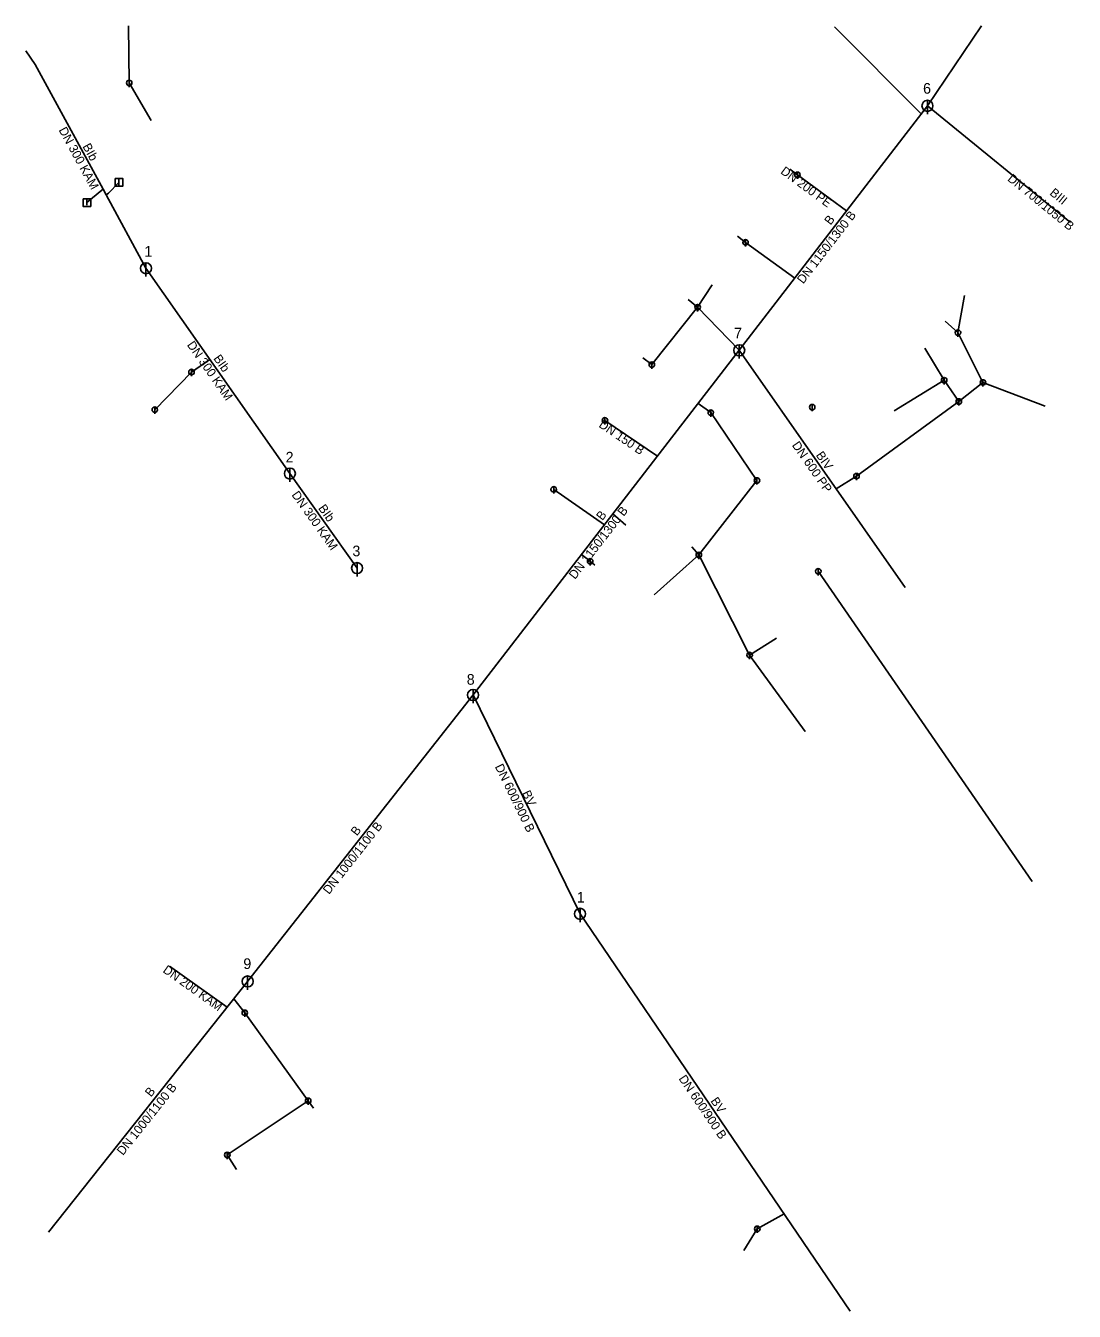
# Model space of a CAD drawing. Extents: x -464767 to -464576, y -1094411 to -1094178.
import ezdxf

# ---------------------------------------------------------------- set-up
doc = ezdxf.new("R2010")
doc.units = 0
for name, color, linetype in [('_pripojka_kanal_destova_prevzato_z_dokumentace_', 7, 'Continuous'), ('_pripojka_kanal_jednotna_prevzato_z_dokumentace_', 7, 'Continuous'), ('_pripojka_kanal_jednotna_priblizne_', 7, 'Continuous'), ('_stoka_jednotna_smvak_prevzato_z_dokumentace_', 7, 'Continuous'), ('Default', 7, 'Continuous'), ('MoLevel 119', 7, 'Continuous'), ('MoLevel 120', 7, 'Continuous'), ('MoLevel 124', 7, 'Continuous'), ('MoLevel 126', 7, 'Continuous'), ('MoLevel 57', 7, 'Continuous'), ('MoLevel 63', 7, 'Continuous'), ('MoLevel 68', 7, 'Continuous'), ('MoLevel 69', 7, 'Continuous')]:
    doc.layers.add(name, color=color, linetype=linetype)

# ---------------------------------------------------------------- blocks, each defined once
blk = doc.blocks.new('_vpust_')
at = {"layer": 'Default'}
blk.add_line((0, 0.000025), (0, -0.000025), dxfattribs=at)
blk.add_lwpolyline([(-0.000035, 0.000035), (0.000035, 0.000035), (0.000035, -0.000035), (-0.000035, -0.000035), (-0.000035, 0.000035)], dxfattribs=at)
blk = doc.blocks.new('_sachta_kanal_prip_')
at = {"layer": 'Default'}
blk.add_line((0, 0.00005), (0, -0.000075), dxfattribs=at)
blk.add_circle((0, 0), 0.00005, dxfattribs=at)
blk = doc.blocks.new('_sachta_kanal_prevzato_z_dokumentace_')
at = {"layer": 'Default'}
blk.add_line((0, 0.00005), (0, -0.000075), dxfattribs=at)
blk.add_circle((0, 0), 0.00005, dxfattribs=at)

msp = doc.modelspace()

# ---------------------------------------------------------------- linework, layer by layer
at = {"layer": '_pripojka_kanal_destova_prevzato_z_dokumentace_'}
for points in [[(-464749.66, -1094205.95), (-464751.57, -1094207.94), (-464751.98, -1094208.2)], [(-464755.46, -1094209.61), (-464752.78, -1094207.36), (-464752.49, -1094207.21)]]:
    msp.add_lwpolyline(points, dxfattribs=at)
at = {"layer": '_pripojka_kanal_jednotna_prevzato_z_dokumentace_'}
for p, q in [((-464619.92, -1094177.74), (-464604.16, -1094193.51)), ((-464628.02, -1094203.58), (-464626.62, -1094204.58)), ((-464626.62, -1094204.58), (-464617.72, -1094211.12)), ((-464637.49, -1094215.73), (-464636.03, -1094216.83)), ((-464636.03, -1094216.83), (-464627.11, -1094223.33)), ((-464642.07, -1094224.53), (-464644.72, -1094228.6)), ((-464653.03, -1094239), (-464644.72, -1094228.6)), ((-464646.44, -1094227.2), (-464644.72, -1094228.6)), ((-464644.72, -1094228.6), (-464637.18, -1094236.41)), ((-464597.52, -1094233.21), (-464592.99, -1094242.24)), ((-464736.5, -1094240.36), (-464733.17, -1094238.06)), ((-464654.63, -1094237.76), (-464653.03, -1094239)), ((-464743.16, -1094247.18), (-464736.5, -1094240.36)), ((-464592.99, -1094242.24), (-464597.36, -1094245.7)), ((-464581.71, -1094246.57), (-464592.99, -1094242.24)), ((-464597.36, -1094245.7), (-464615.92, -1094259.23)), ((-464633.97, -1094260.02), (-464642.34, -1094247.72)), ((-464661.53, -1094249.13), (-464652.01, -1094255.62)), ((-464615.92, -1094259.23), (-464619.59, -1094261.55)), ((-464670.81, -1094261.64), (-464661.61, -1094268.05)), ((-464664.21, -1094274.68), (-464665.77, -1094273.44)), ((-464663.38, -1094275.37), (-464664.21, -1094274.68)), ((-464622.85, -1094276.5), (-464584.08, -1094332.75)), ((-464726.84, -1094356.57), (-464728.83, -1094354.05)), ((-464715.34, -1094372.53), (-464726.84, -1094356.57)), ((-464730.01, -1094382.35), (-464715.34, -1094372.53)), ((-464714.38, -1094373.89), (-464715.34, -1094372.53)), ((-464728.31, -1094385.02), (-464730.01, -1094382.35))]:
    msp.add_line(p, q, dxfattribs=at)
for points in [[(-464642.34, -1094247.72), (-464642.34, -1094247.72), (-464644.62, -1094246.05)], [(-464644.51, -1094273.52), (-464644.51, -1094273.52), (-464633.97, -1094260.02)], [(-464635.3, -1094291.68), (-464635.3, -1094291.68), (-464644.51, -1094273.52)], [(-464625.24, -1094305.57), (-464625.24, -1094305.57), (-464635.3, -1094291.68)]]:
    msp.add_lwpolyline(points, dxfattribs=at)
at = {"layer": '_pripojka_kanal_jednotna_priblizne_'}
for p, q in [((-464747.79, -1094187.91), (-464747.91, -1094177.54)), ((-464743.79, -1094194.73), (-464747.79, -1094187.91)), ((-464596.32, -1094226.5), (-464597.52, -1094233.21)), ((-464599.83, -1094231.13), (-464597.52, -1094233.21)), ((-464603.55, -1094236.05), (-464600.02, -1094241.84)), ((-464609.09, -1094247.39), (-464600.02, -1094241.84)), ((-464600.02, -1094241.84), (-464597.36, -1094245.7)), ((-464657.77, -1094268.12), (-464660.1, -1094266.1)), ((-464652.62, -1094280.74), (-464644.51, -1094273.52)), ((-464645.75, -1094272.04), (-464644.51, -1094273.52)), ((-464630.4, -1094288.62), (-464635.3, -1094291.68)), ((-464740.49, -1094348.1), (-464730.01, -1094355.53)), ((-464633.91, -1094395.75), (-464629.05, -1094393.06)), ((-464636.36, -1094399.67), (-464633.91, -1094395.75))]:
    msp.add_line(p, q, dxfattribs=at)
at = {"layer": '_stoka_jednotna_smvak_prevzato_z_dokumentace_'}
for p, q in [((-464603.05, -1094192.07), (-464593.24, -1094177.54)), ((-464637.18, -1094236.41), (-464603.05, -1094192.07)), ((-464577.13, -1094213.22), (-464603.05, -1094192.07)), ((-464718.66, -1094258.76), (-464744.75, -1094221.53)), ((-464685.45, -1094298.93), (-464637.18, -1094236.41)), ((-464607.1, -1094279.41), (-464637.18, -1094236.41)), ((-464706.47, -1094275.92), (-464718.66, -1094258.76)), ((-464726.32, -1094350.89), (-464685.45, -1094298.93)), ((-464666.04, -1094338.62), (-464685.45, -1094298.93)), ((-464617.06, -1094410.71), (-464666.04, -1094338.62)), ((-464762.44, -1094396.33), (-464726.32, -1094350.89))]:
    msp.add_line(p, q, dxfattribs=at)
msp.add_lwpolyline([(-464744.75, -1094221.53), (-464751.98, -1094208.2), (-464752.49, -1094207.21), (-464764.84, -1094184.6), (-464766.56, -1094182.1)], dxfattribs=at)

# ---------------------------------------------------------------- block references
at = {"layer": 'MoLevel 119', "xscale": 20000, "yscale": 20000}
for p in [(-464603.05, -1094192.07), (-464744.75, -1094221.53), (-464637.18, -1094236.41), (-464718.66, -1094258.76), (-464706.47, -1094275.92), (-464685.45, -1094298.93), (-464666.04, -1094338.62), (-464726.32, -1094350.89)]:
    msp.add_blockref('_sachta_kanal_prevzato_z_dokumentace_', p, dxfattribs=at)
at = {"layer": 'MoLevel 57', "xscale": 10000, "yscale": 10000}
for p in [(-464747.79, -1094187.91), (-464626.62, -1094204.58), (-464636.03, -1094216.83), (-464644.72, -1094228.6), (-464597.52, -1094233.21), (-464653.03, -1094239), (-464736.5, -1094240.36), (-464600.02, -1094241.84), (-464592.99, -1094242.24), (-464597.36, -1094245.7), (-464743.16, -1094247.18), (-464642.34, -1094247.72), (-464623.94, -1094246.72), (-464661.53, -1094249.13), (-464633.97, -1094260.02), (-464615.92, -1094259.23), (-464670.81, -1094261.64), (-464644.51, -1094273.52), (-464664.21, -1094274.68), (-464622.85, -1094276.5), (-464635.3, -1094291.68), (-464726.84, -1094356.57), (-464715.34, -1094372.53), (-464730.01, -1094382.35), (-464633.91, -1094395.75)]:
    msp.add_blockref('_sachta_kanal_prip_', p, dxfattribs=at)
at = {"layer": 'MoLevel 63', "xscale": 20000, "yscale": 20000}
for p in [(-464749.66, -1094205.95), (-464755.46, -1094209.61)]:
    msp.add_blockref('_vpust_', p, dxfattribs=at)

# ---------------------------------------------------------------- texts
at = {"layer": 'MoLevel 120'}
for s, p in [('6', (-464603.84, -1094189.87)), ('1', (-464745.05, -1094219.44)), ('7', (-464638.11, -1094234.25)), ('2', (-464719.43, -1094256.76)), ('3', (-464707.32, -1094273.77)), ('8', (-464686.58, -1094297.07)), ('1', (-464666.62, -1094336.57)), ('9', (-464727.1, -1094348.63))]:
    msp.add_text(s, height=1.93, dxfattribs=at).set_placement(p)
at = {"layer": 'MoLevel 124'}
msp.add_text('DN 200 KAM', height=1.605, rotation=324.667, dxfattribs=at).set_placement((-464741.82, -1094349.12))
at = {"layer": 'MoLevel 126'}
for s, rotation, p in [('DN 200 PE', 323.6815, (-464629.81, -1094204.23)), ('DN 150 B', 325.7072, (-464662.78, -1094250.22))]:
    msp.add_text(s, height=1.605, rotation=rotation, dxfattribs=at).set_placement(p)
at = {"layer": 'MoLevel 68'}
for s, height, rotation, p in [('DN 300 KAM', 1.605, 298.6442, (-464760.63, -1094196.45)), ('DN 700/1050 B', 1.6049, 320.7959, (-464588.65, -1094205.53)), ('DN 1150/1300 B', 1.6049, 52.4133, (-464625.57, -1094224.47)), ('DN 300 KAM', 1.605, 305.022, (-464737.39, -1094235.44)), ('DN 600 PP', 1.605, 304.9741, (-464627.69, -1094253.63)), ('DN 300 KAM', 1.605, 305.389, (-464718.42, -1094262.64)), ('DN 1150/1300 B', 1.6049, 52.3292, (-464666.95, -1094278.06)), ('DN 600/900 B', 1.6049, 296.0605, (-464681.52, -1094311.91)), ('DN 1000/1100 B', 1.6049, 51.8126, (-464711.56, -1094335.2)), ('DN 1000/1100 B', 1.6049, 51.519, (-464748.93, -1094382.54)), ('DN 600/900 B', 1.6049, 304.1933, (-464648.23, -1094368.52))]:
    msp.add_text(s, height=height, rotation=rotation, dxfattribs=at).set_placement(p)
at = {"layer": 'MoLevel 69'}
for s, height, rotation, p in [('BIb', 1.605, 298.6442, (-464756.31, -1094199.41)), ('BIII', 1.605, 320.7959, (-464581.01, -1094208.09)), ('B', 1.6, 52.4133, (-464620.62, -1094213.81)), ('BIb', 1.605, 305.022, (-464732.59, -1094237.89)), ('BIV', 1.605, 304.9741, (-464623.35, -1094255.43)), ('BIb', 1.605, 305.389, (-464713.59, -1094265.06)), ('B', 1.6, 52.3292, (-464661.99, -1094267.4)), ('BV', 1.605, 296.0605, (-464676.6, -1094316.71)), ('B', 1.6, 51.8126, (-464706.51, -1094324.59)), ('B', 1.6, 51.519, (-464743.84, -1094371.95)), ('BV', 1.605, 304.1933, (-464642.45, -1094372.56))]:
    msp.add_text(s, height=height, rotation=rotation, dxfattribs=at).set_placement(p)

doc.saveas('drawing.dxf')
